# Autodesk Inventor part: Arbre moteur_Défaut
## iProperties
Shininess: 64.0
Length Units: 11269
Angle Units: 11279
Time Units: 11290
Mass Units: 11283
Length Display Precision: 3
Angle Display Precision: 2
Compacted: True
Part Number: Arbre moteur_Défaut
Document SubType Name: Modeling
Created: 2006-01
Material: Par défaut
Designer: Fricot
Density: 0.0
Volumn: 0.0
Area: 0.0
PropertySet Name: Model Information
Control State: 0
Master: False
Checked Out: False
Author: Fricot
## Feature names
1. Base1
